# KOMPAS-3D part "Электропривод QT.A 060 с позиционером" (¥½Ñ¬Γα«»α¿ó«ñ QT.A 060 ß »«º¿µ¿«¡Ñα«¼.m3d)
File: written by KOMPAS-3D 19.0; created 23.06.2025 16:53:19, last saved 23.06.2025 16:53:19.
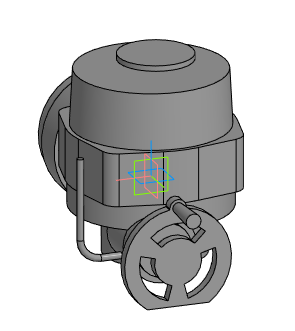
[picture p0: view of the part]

Document properties: Автор: Евгений; Полное имя файла: E:\Dendor Работа Сачек\3D для проектировщиков\3.5 Тип QT.А Электропривод\stp_Электропривод QT.A с позиционером\Электропривод QT.A 060 с позиционером.m3d

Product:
- Part/product: Электропривод QT.A 060 с позиционером

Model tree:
1. Операция без истории:1  (labels: Электропривод QT.A 060 с позиционером)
